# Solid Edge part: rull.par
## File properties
Author: Mac
Template: Normal.par
Last saved by: Mac
Revision: 1
Application: Solid Edge
Accuracy: 0,990
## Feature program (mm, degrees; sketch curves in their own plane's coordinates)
sketch for "unnamed Protrusion 1" #1 plane through (0, 0, 0) normal (0, 0, 1) x-axis (1, 0, 0)
  circle centre (0, 0) radius 0.08
sketch for "unnamed Protrusion 1" #2 plane through (0, 0, 0) normal (0, 0, 1) x-axis (1, 0, 0)
  circle centre (0, 0) radius 0.3
extrude "unnamed Protrusion 1" add finite 0.47 along +normal
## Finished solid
Body 1: solid body, 4 faces, 4 edges, 0 vertices.
  Faces by surface: cylinder 2, plane 2
  Edges by curve: circle 4
Bounding box of the edges (mm): 0.600 x 0.600 x 0.470, from (-0.3, -0.3, 0) to (0.3, 0.3, 0.47).
Cylindrical faces by radius (mm): R0.08 x1, R0.3 x1
Planar faces by outward normal: +z 1, -z 1
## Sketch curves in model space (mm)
circle centre (0, 0, 0) radius 0.3
circle centre (0, 0, 0) radius 0.08
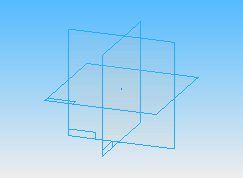
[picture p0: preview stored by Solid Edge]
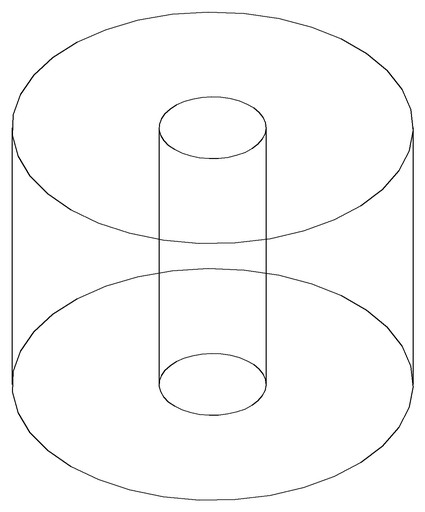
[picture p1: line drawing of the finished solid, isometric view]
